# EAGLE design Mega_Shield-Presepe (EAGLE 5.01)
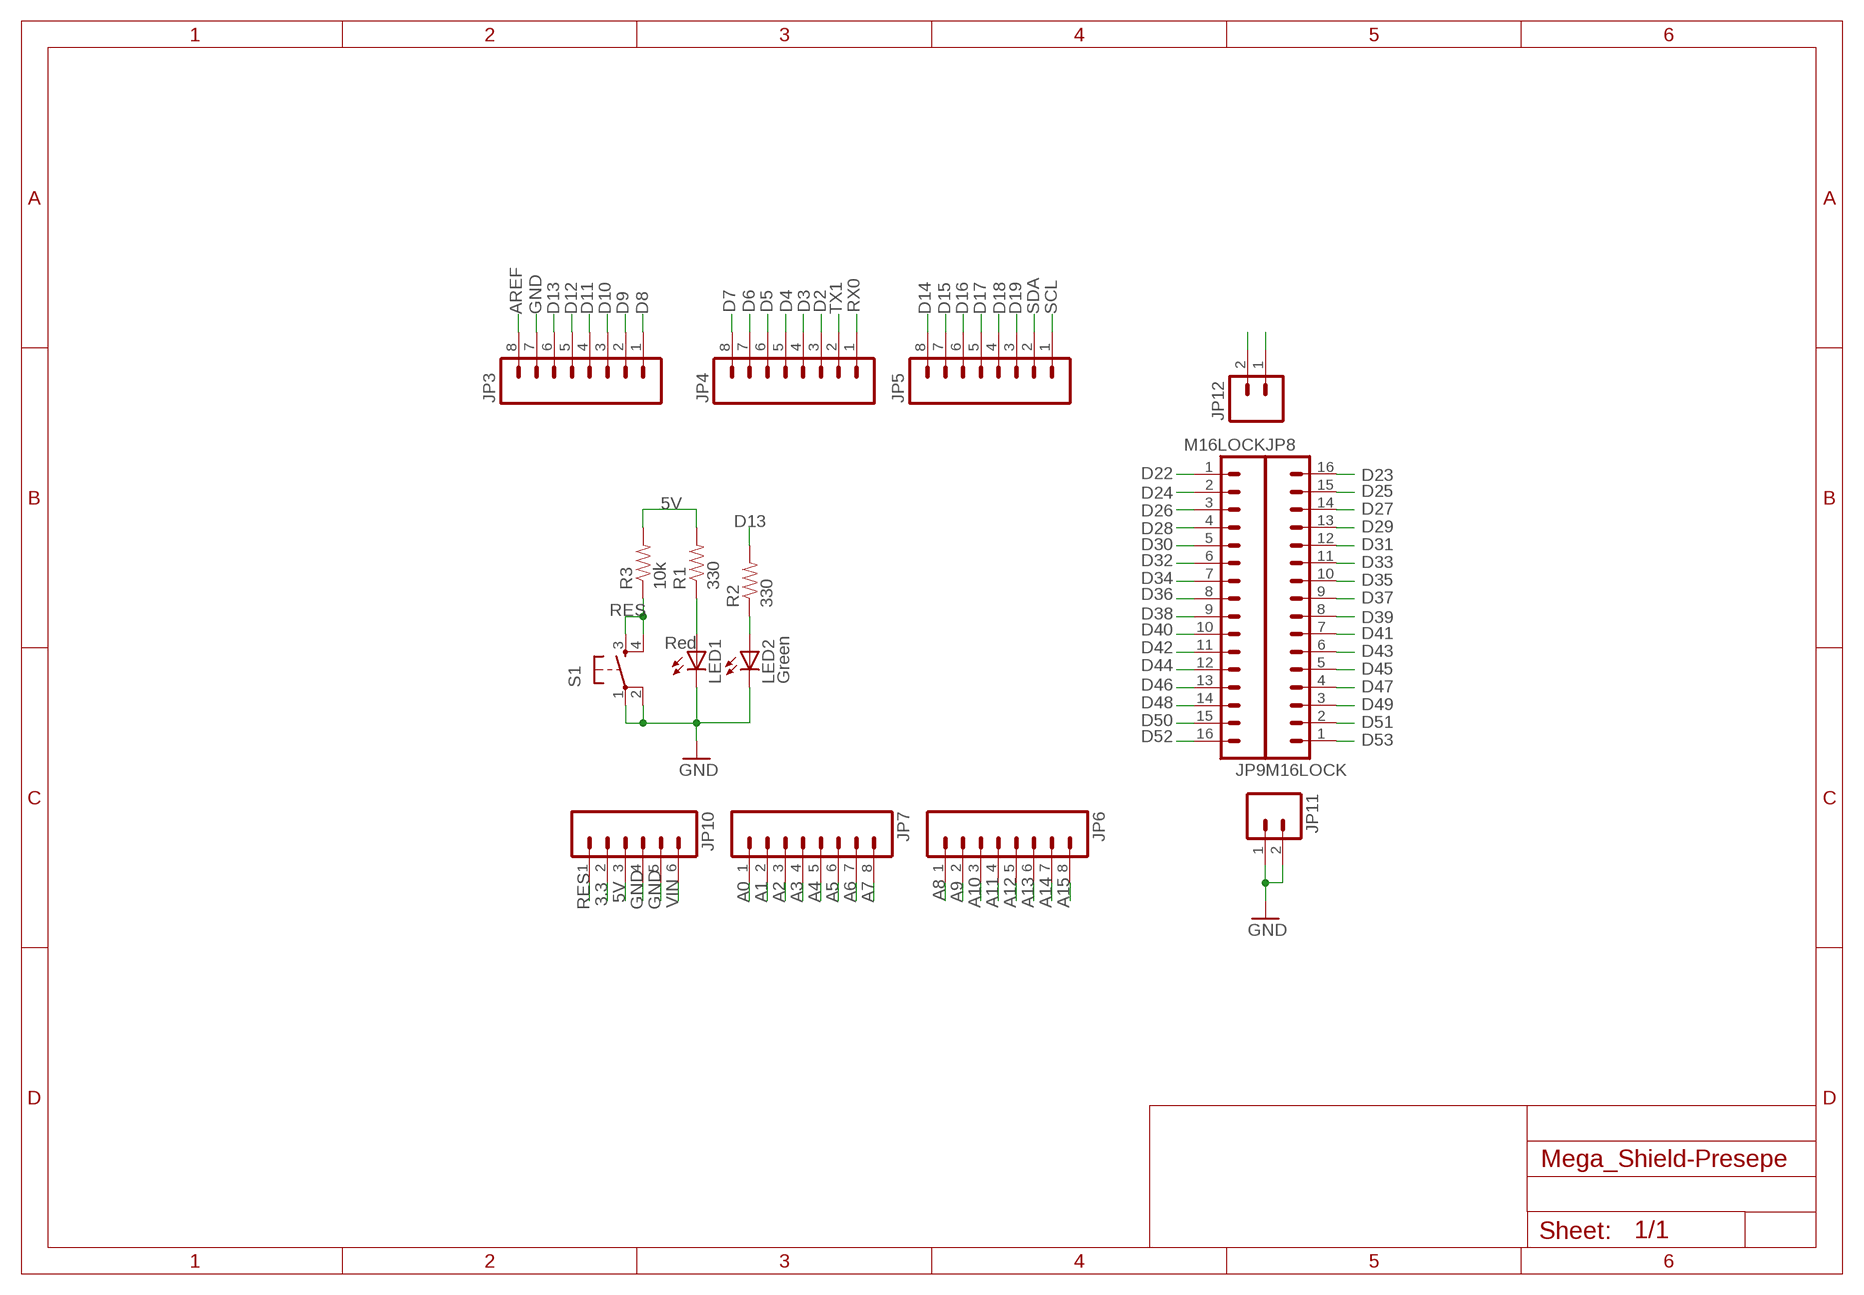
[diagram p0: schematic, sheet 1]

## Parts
JP3  M08LOCK  [1X08_LOCK]
JP4  M08LOCK  [1X08_LOCK]
JP5  M08LOCK  [1X08_LOCK]
JP6  M08LOCK  [1X08_LOCK]
JP7  M08LOCK  [1X08_LOCK]
JP8  M16LOCK  [1X16_LOCK]
JP9  M16LOCK  [1X16_LOCK]
JP10  M06LOCK  [1X06_LOCK]
JP11  M02LOCK  [1X02_LOCK]
JP12  M02LOCK  [1X02_LOCK]
LED1  Red  LED5MM  [LED5MM]
LED2  Green  LED5MM  [LED5MM]
R1  330  RESISTORPTH1  [AXIAL-0.3]
R2  330  RESISTORPTH1  [AXIAL-0.3]
R3  10k  RESISTORPTH1  [AXIAL-0.3]
S1  TAC_SWITCHPTH  [TACTILE-PTH]

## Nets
3.3: JP10.2
5V: JP10.3 R1.P$2 R3.P$2
5V@1: JP12.1 JP12.2
A0: JP7.1
A1: JP7.2
A2: JP7.3
A3: JP7.4
A4: JP7.5
A5: JP7.6
A6: JP7.7
A7: JP7.8
A8: JP6.1
A9: JP6.2
A10: JP6.3
A11: JP6.4
A12: JP6.5
A13: JP6.6
A14: JP6.7
A15: JP6.8
AREF: JP3.8
D2: JP4.3
D3: JP4.4
D4: JP4.5
D5: JP4.6
D6: JP4.7
D7: JP4.8
D8: JP3.1
D9: JP3.2
D10: JP3.3
D11: JP3.4
D12: JP3.5
D13: JP3.6 R2.P$2
D14: JP5.8
D15: JP5.7
D16: JP5.6
D17: JP5.5
D18: JP5.4
D19: JP5.3
D22: JP9.1
D23: JP8.16
D24: JP9.2
D25: JP8.15
D26: JP9.3
D27: JP8.14
D28: JP9.4
D29: JP8.13
D30: JP9.5
D31: JP8.12
D32: JP9.6
D33: JP8.11
D34: JP9.7
D35: JP8.10
D36: JP9.8
D37: JP8.9
D38: JP9.9
D39: JP8.8
D40: JP9.10
D41: JP8.7
D42: JP9.11
D43: JP8.6
D44: JP9.12
D45: JP8.5
D46: JP9.13
D47: JP8.4
D48: JP9.14
D49: JP8.3
D50: JP9.15
D51: JP8.2
D52: JP9.16
D53: JP8.1
GND: JP3.7 JP10.4 JP10.5 JP11.1 JP11.2 LED1.K(C) LED2.K(C) S1.1 S1.2
N$126: LED1.A R1.P$1
N$127: LED2.A R2.P$1
RES: JP10.1 R3.P$1 S1.3 S1.4
RX0: JP4.1
SCL: JP5.1
SDA: JP5.2
TX1: JP4.2
VIN: JP10.6

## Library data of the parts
JP3-JP7 = SparkFun:M08: Header 8 Standard 8-pin 0.1" header. Use with straight break away headers (SKU : PRT-00116), right angle break away headers (PRT-00553), swiss pins (PRT-00743), machine pins (PRT-00117), and female headers (PRT-00115).
JP8 JP9 = SparkFun:M16
JP10 = SparkFun:M06: Header 6 Standard 6-pin 0.1" header. Use with straight break away headers (SKU : PRT-00116), right angle break away headers (PRT-00553), swiss pins (PRT-00743), machine pins (PRT-00117), and female headers (PRT-00115). Molex polarized connector foot print use with SKU : PRT-08094 with associated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
JP11 JP12 = SparkFun:M02: Header 2
LED1 LED2 = SparkFun:LED: LEDs
R1-R3 = SparkFun:RESISTOR: Resistor
S1 = SparkFun:TAC_SWITCH: Momentary Switch Button commonly used for reset or general input. Spark Fun Electronics SKU : COM-00097

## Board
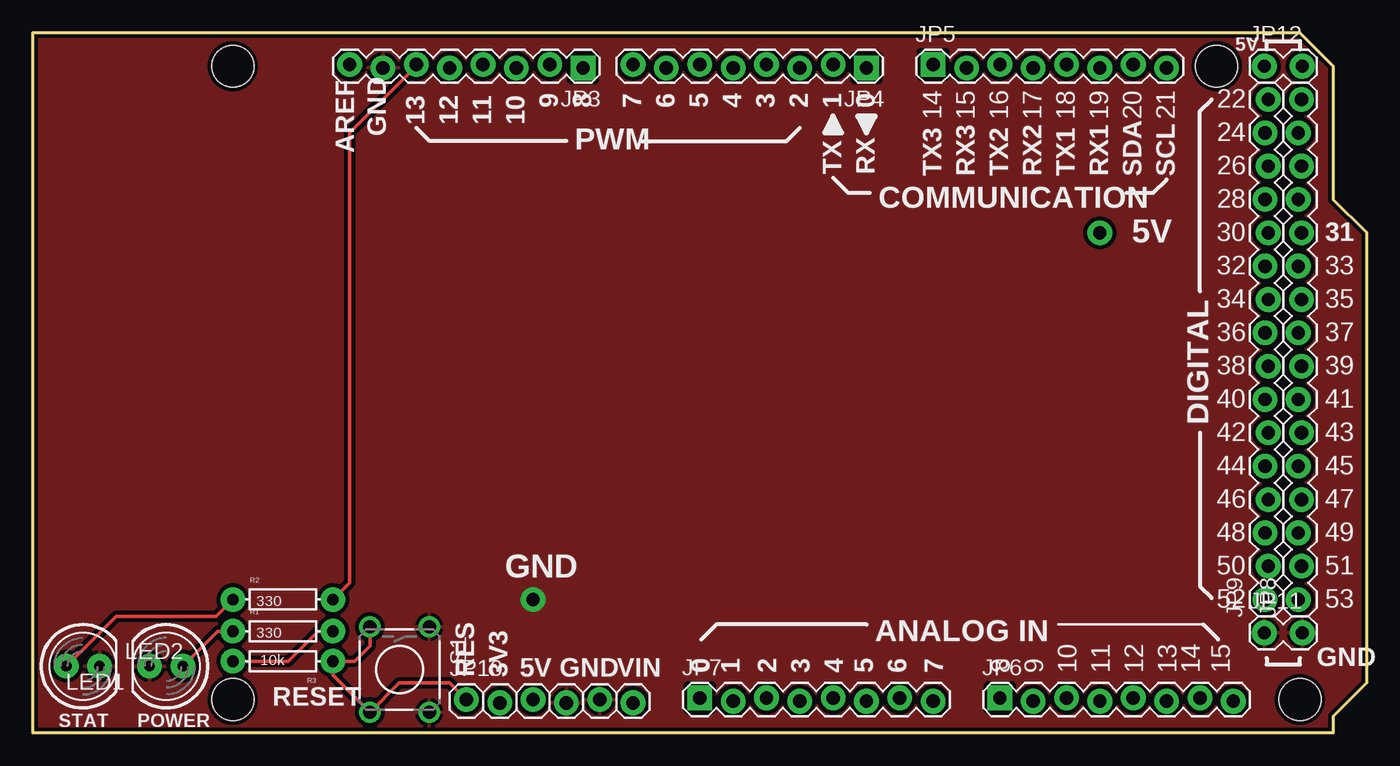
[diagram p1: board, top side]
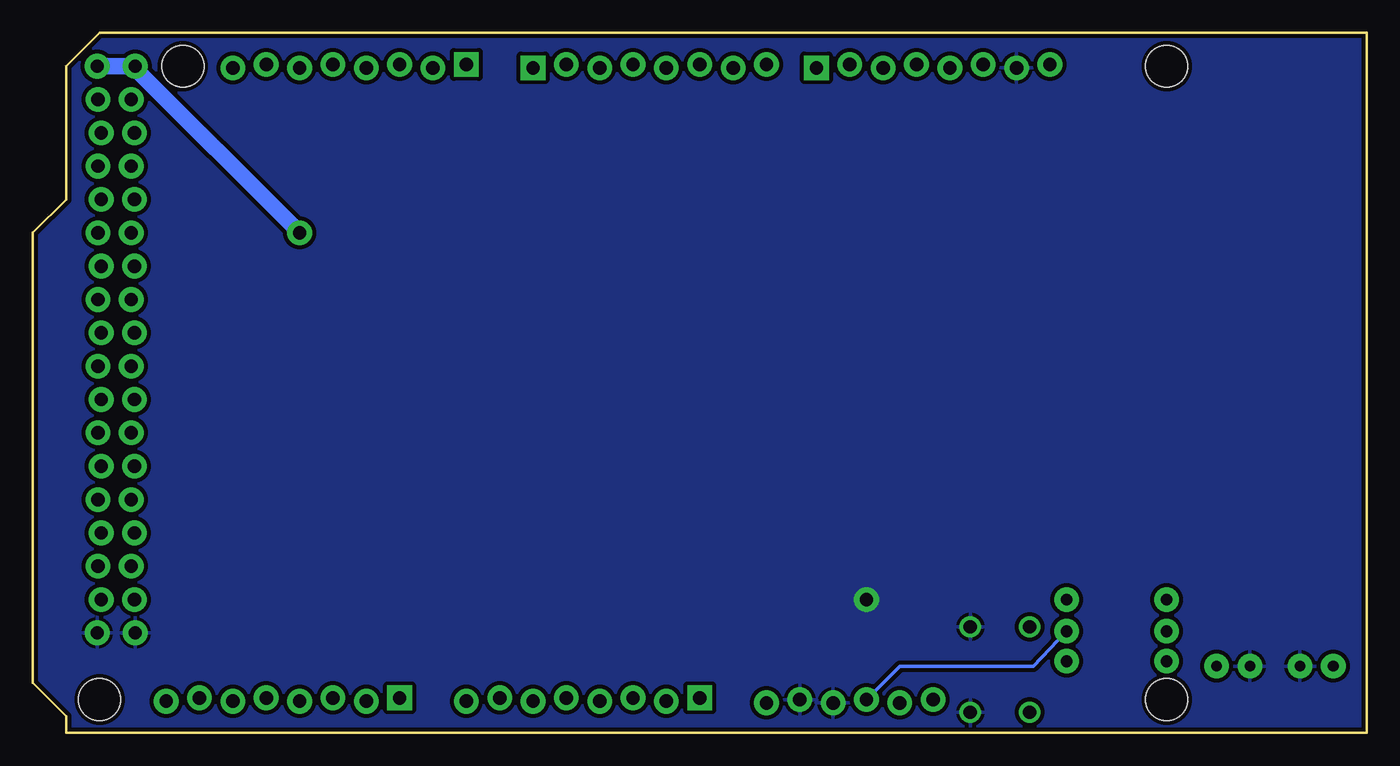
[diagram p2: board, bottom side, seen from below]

Size 101.6 x 53.34 mm. Coordinates in mm from the lower left corner, seen from the top.
Outline: 0,0 99.06,0 99.06,1.27 101.6,3.81 101.6,38.1 99.06,40.64 99.06,50.8 96.52,53.34 0,53.34 0,0
Copper layers (1*16): Top 0.035mm / dielectric 1.5mm / Bottom 0.035mm
Design rules "SparkFun": minimum track width 8mil, minimum drill 20mil, track to track 8mil, track to pad 8mil, pad to pad 8mil, via to via 8mil, smd to smd 8mil, copper to edge 10mil, drill to drill 8mil, minimum pad ring 12mil, minimum via ring 10mil, stop-mask expansion 4mil, vias tented up to drill 25mil, thermal gap 10mil
Holes 3.2 mm at 15.24,50.8 15.24,2.54 90.17,50.8 96.52,2.54

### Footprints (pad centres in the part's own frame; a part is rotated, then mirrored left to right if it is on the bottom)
1X08_LOCK = drill 1.016 pad 1.88 square: 1 0,0.127 | drill 1.016 pad 1.88 round: 2 2.54,-0.127; 3 5.08,0.127; 4 7.62,-0.127; 5 10.16,0.127; 6 12.7,-0.127; 7 15.24,0.127; 8 17.78,-0.127
1X16_LOCK = drill 1.016 pad 1.88 round: 1 0,0.127; 2 2.54,-0.127; 3 5.08,0.127; 4 7.62,-0.127; 5 10.16,0.127; 6 12.7,-0.127; 7 15.24,0.127; 8 17.78,-0.127; 9 20.32,0.127; 10 22.86,-0.127; 11 25.4,0.127; 12 27.94,-0.127; 13 30.48,0.127; 14 33.02,-0.127; 15 35.56,0.127; 16 38.1,-0.127
1X06_LOCK = drill 1.016 pad 1.88 round: 1 0,0; 2 2.54,-0.254; 3 5.08,0; 4 7.62,-0.254; 5 10.16,0; 6 12.7,-0.254
1X02_LOCK = drill 1.016 pad 1.88 round: 1 -0.178,0; 2 2.718,0
LED5MM = drill 0.813 pad 1.88 round: A -1.27,0; K 1.27,0
AXIAL-0.3 = drill 0.9 pad 1.88 round: P$1 -3.81,0; P$2 3.81,0
TACTILE-PTH = drill 1.016 round: 1 -3.251,2.261; 2 3.251,2.261; 3 -3.251,-2.261; 4 3.251,-2.261

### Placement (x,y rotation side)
JP3  41.91,50.8 180 top
JP4  63.5,50.8 180 top
JP5  68.58,50.8 0 top
JP6  73.66,2.54 0 top
JP7  50.8,2.54 0 top
JP8  96.52,10.16 90 top
JP9  93.98,10.16 90 top
JP10  33.02,2.54 0 top
JP11  93.98,7.62 0 top
JP12  93.98,50.8 0 top
LED1  10.16,5.08 180 top
LED2  3.81,5.08 0 top
R1  19.05,7.75 0 top
R2  19.05,10.16 0 top
R3  19.05,5.46 180 top
S1  27.94,4.83 270 top

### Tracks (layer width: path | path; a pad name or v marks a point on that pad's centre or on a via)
3.3
  Top 0.203: JP10.2 35.56,2.54 JP10.2
5V
  Top 0.254: R3.P$2 19.43,5.46 21.72,7.75 R1.P$2
  Bottom 0.254: R1.P$2 25.4,5.08 35.56,5.08 JP10.3
5V@1  (via drill 1.02 pad 1.88)
  Bottom 1.27: v81.28,38.1 93.98,50.8 JP12.1 JP12.2
A0
  Top 0.203: JP7.1 50.8,2.54
A1
  Top 0.203: JP7.2 53.34,2.54 JP7.2
A2
  Top 0.203: JP7.3 55.88,2.54
A3
  Top 0.203: JP7.4 58.42,2.54 JP7.4
A4
  Top 0.203: JP7.5 60.96,2.54
A5
  Top 0.203: JP7.6 63.5,2.54 JP7.6
A6
  Top 0.203: JP7.7 66.04,2.54
A7
  Top 0.203: JP7.8 68.58,2.54 JP7.8
A8
  Top 0.203: JP6.1 73.66,2.54
A9
  Top 0.203: JP6.2 76.2,2.54 JP6.2
A10
  Top 0.203: JP6.3 78.74,2.54
A11
  Top 0.203: JP6.4 81.28,2.54 JP6.4
A12
  Top 0.203: JP6.5 83.82,2.54
A13
  Top 0.203: JP6.6 86.36,2.54 JP6.6
A14
  Top 0.203: JP6.7 88.9,2.54
A15
  Top 0.203: JP6.8 91.44,2.54 JP6.8
AREF
  Top 0.203: JP3.8 24.13,50.8 JP3.8
D2
  Top 0.203: JP4.3 58.42,50.8
D3
  Top 0.203: JP4.4 55.88,50.8 JP4.4
D4
  Top 0.203: JP4.5 53.34,50.8
D5
  Top 0.203: JP4.6 50.8,50.8 JP4.6
D6
  Top 0.203: JP4.7 48.26,50.8
D7
  Top 0.203: JP4.8 45.72,50.8 JP4.8
D8
  Top 0.203: JP3.1 41.91,50.8
D9
  Top 0.203: JP3.2 39.37,50.8 JP3.2
D10
  Top 0.203: JP3.3 36.83,50.8
D11
  Top 0.203: JP3.4 34.29,50.8 JP3.4
D12
  Top 0.203: JP3.5 31.75,50.8
D13
  Top 0.254: R2.P$2 24.13,11.43 24.13,12.7 24.13,45.72 29.21,50.8 JP3.6
D14
  Top 0.203: JP5.8 86.36,50.8
D15
  Top 0.203: JP5.7 83.82,50.8 JP5.7
D16
  Top 0.203: JP5.6 81.28,50.8
D17
  Top 0.203: JP5.5 78.74,50.8 JP5.5
D18
  Top 0.203: JP5.4 76.2,50.8
D19
  Top 0.203: JP5.3 73.66,50.8 JP5.3
GND  (via drill 1.02 pad 1.88)
  other vias: 38.1,10.16 38.1,10.16 38.1,10.16 38.1,10.16 38.1,10.16 38.1,10.16 38.1,10.16 38.1,10.16 38.1,10.16 38.1,10.16 38.1,10.16 38.1,10.16 38.1,10.16 38.1,10.16 38.1,10.16 38.1,10.16 38.1,10.16 38.1,10.16 38.1,10.16 38.1,10.16 38.1,10.16
  pour Bottom (isolate 0.305): 0,0 99.06,0 99.06,1.27 101.6,3.81 101.6,38.1 99.06,40.64 99.06,50.8 96.52,53.34 0,53.34 0,2.54
  pour Top (isolate 0.305): 0,0 99.06,0 99.06,1.27 101.6,3.81 101.6,38.1 99.06,40.64 99.06,50.8 96.52,53.34 0,53.34 0,2.54
N$126
  Top 0.254: R1.P$1 14.1,7.75 LED1.A
N$127
  Top 0.254: R2.P$1 13.97,8.89 6.35,8.89 LED2.A
RES
  Top 0.254: JP10.1 31.75,3.81 27.91,3.81 S1.4 22.86,4.39 R3.P$1 24.51,5.46 25.68,6.63 S1.3
RX0
  Top 0.203: JP4.1 63.5,50.8
SCL
  Top 0.203: JP5.1 68.58,50.8 JP5.1
SDA
  Top 0.203: JP5.2 71.12,50.8
TX1
  Top 0.203: JP4.2 60.96,50.8 JP4.2
VIN
  Top 0.203: JP10.6 45.72,2.54 JP10.6

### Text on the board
tPlace: 5V | 9 | 8 | 7 | 6 | 5 | 4 | 3 | 2 | 1 | 0 | 22 | 14 | 15 | 16 | 17 | 18 | 19 | 20 | 21 | 13 | 12 | 11 | 10 | GND | 24 | AREF | PWM | TX | RX | 26 | TX3 | RX3 | TX2 | RX2 | TX1 | RX1 | SDA | SCL | COMMUNICATION | 28 | 5V | 30 | 31 | 32 | 33 | 34 | 35 | 36 | 37 | 38 | 39 | 40 | 41 | DIGITAL | 42 | 43 | 44 | 45 | 46 | 47 | 48 | 49 | GND | 50 | 51 | 52 | 53 | ANALOG IN | 0 | 1 | 2 | 3 | 4 | 5 | 6 | 7 | 8 | 9 | 10 | 11 | 12 | 13 | 14 | 15 | GND | RES | 3V3 | 5V | GND | VIN | RESET | STAT | POWER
